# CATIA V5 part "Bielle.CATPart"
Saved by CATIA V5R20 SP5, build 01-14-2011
Part number: Bielle
Publications: "Longueur_bielle"
Bounding box of the stored display mesh (mm): x -64.99 to 4.99, y 0 to 5, z -5 to 5
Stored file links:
  D:\Dropbox\IAO_2011\MMS_GR3\IAO_2011_1475_rguinot\IAO\IAO_2011_1475_rguinot\Bielle.CATPart
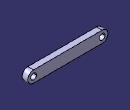
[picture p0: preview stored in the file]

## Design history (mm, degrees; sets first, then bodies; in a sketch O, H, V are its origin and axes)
Parameters
  Longueur_bielle = 60 mm
Body1 (main body)
  Sketch1 on zx-plane, origin (0, 0, 0), H (-1, 0, 0), V (0, 0, 1)
    arc A1 centre (0, 0) radius 5 from (0, 5) to (0, -5) ccw
    arc A2 centre (60, 0) radius 5 from (60, -5) to (60, 5) ccw
    point P1 (60, 0)
    line L1 (0, 5) -> (60, 5)
    point P2 (0, 5)
    line L2 (60, -5) -> (0, -5)
    circle A3 centre (60, 0) radius 2.5
    circle A4 centre (0, 0) radius 2.5
    radius A1 = 5
    radius A2 = 5
    distance P1 O = 60 {= Longueur_bielle}
    radius A3 = 2.5
    radius A4 = 2.5
    coincidence: P1 H, P2 V
    tangency: L1 A2, L2 A1, L2 A2
  Pad1: profile Sketch1, direction (0, 1, 0), length 5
